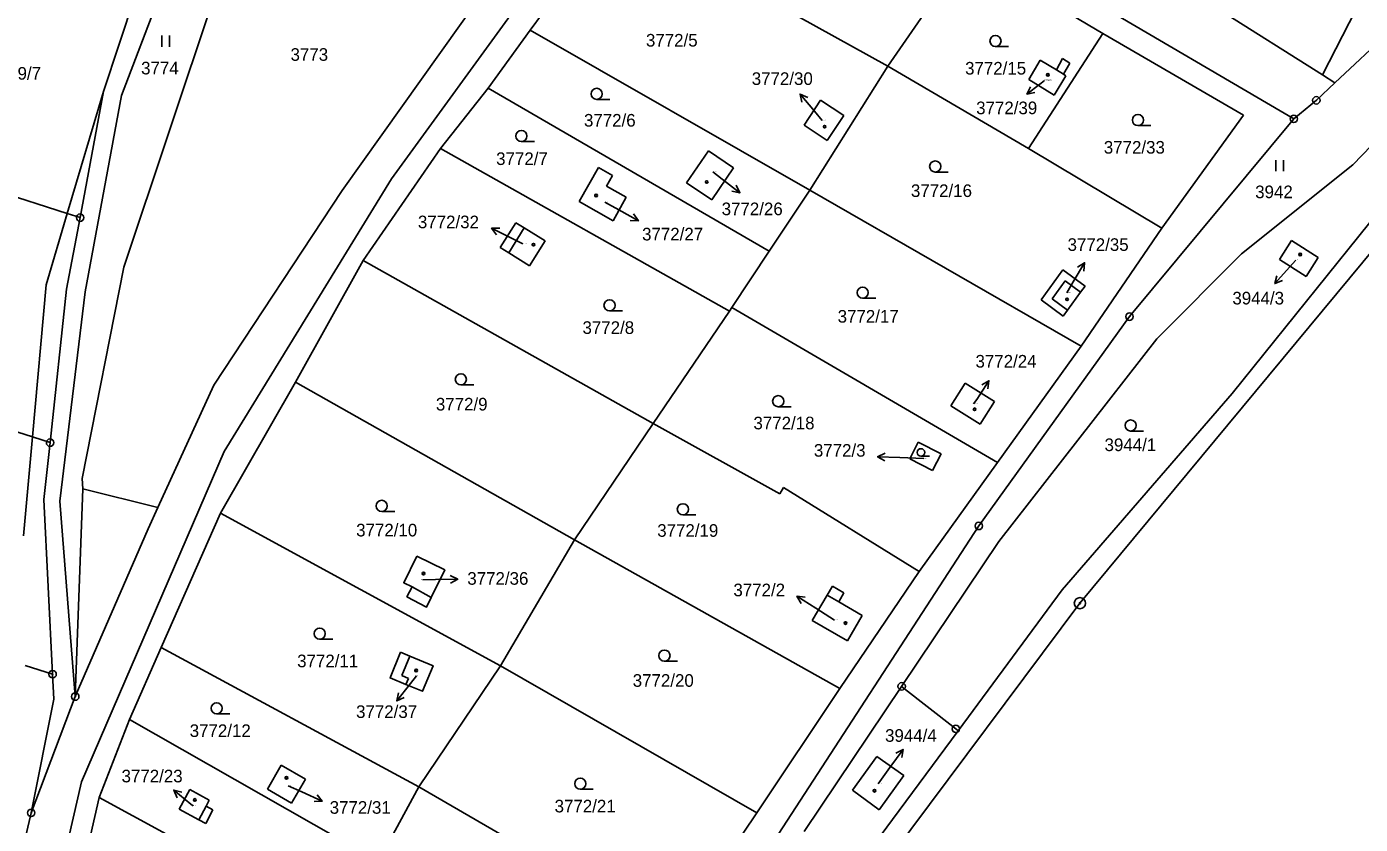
# Model space of a CAD drawing. Extents: x -593183 to -588034, y -1130415 to -1124994.
# Drawn here: x -592165.9 to -591986.4, y -1129394.8 to -1129287.4 of the extents above; entities that cross this region are included whole.
import ezdxf

# ---------------------------------------------------------------- set-up
doc = ezdxf.new("R2010")
doc.units = 0
for name, color, linetype in [('Vrstva 1', 7, 'Continuous'), ('Vrstva 16', 7, 'Continuous'), ('Vrstva 18', 7, 'Continuous'), ('Vrstva 19', 7, 'Continuous'), ('Vrstva 24', 7, 'Continuous'), ('Vrstva 25', 7, 'Continuous'), ('Vrstva 4', 7, 'Continuous')]:
    doc.layers.add(name, color=color, linetype=linetype)

msp = doc.modelspace()

# ---------------------------------------------------------------- linework, layer by layer
at = {"layer": 'Vrstva 1'}
for p, q in [((-591991.53, -1129293.86), (-591952.91, -1129218.61)), ((-592116.8, -1129307.85), (-592076.4, -1129252.25)), ((-592145, -1129264.2), (-592155.57, -1129296.12)), ((-592044.4, -1129271.02), (-591995.38, -1129299.79)), ((-592098.13, -1129287.85), (-592086.76, -1129272.18)), ((-592086.76, -1129272.18), (-592050.02, -1129292.7)), ((-592145.24, -1129275.92), (-592153.15, -1129296.63)), ((-592039.44, -1129277.39), (-592050.02, -1129292.7)), ((-592021.07, -1129288.3), (-592039.44, -1129277.39)), ((-592123.43, -1129309.45), (-592101.67, -1129278.83)), ((-591989.84, -1129294.93), (-591974.47, -1129280.49)), ((-592139.87, -1129280.88), (-592152.85, -1129319.75)), ((-592005.49, -1129285.08), (-591991.53, -1129293.86)), ((-592103.79, -1129295.64), (-592098.13, -1129287.85)), ((-592098.13, -1129287.85), (-592060.52, -1129309.39)), ((-592031.08, -1129303.8), (-592021.07, -1129288.3)), ((-592021.07, -1129288.3), (-592002.16, -1129299.31)), ((-592050.02, -1129292.7), (-592060.52, -1129309.39)), ((-592050.02, -1129292.7), (-592031.08, -1129303.8)), ((-592029.5, -1129291.89), (-592031.05, -1129294.47)), ((-592029.5, -1129291.89), (-592027.32, -1129293.19)), ((-592026.49, -1129291.68), (-592027.32, -1129293.19)), ((-592026.49, -1129291.68), (-592025.54, -1129292.28)), ((-592025.54, -1129292.28), (-592026.36, -1129293.76)), ((-592031.05, -1129294.47), (-592027.65, -1129296.58)), ((-592026.06, -1129293.98), (-592027.65, -1129296.58)), ((-592026.36, -1129293.76), (-592026.06, -1129293.98)), ((-591989.84, -1129294.93), (-591992.35, -1129297.29)), ((-591991.53, -1129293.86), (-591989.84, -1129294.93)), ((-592158.72, -1129313.09), (-592155.57, -1129296.12)), ((-592153.15, -1129296.63), (-592158.02, -1129323.08)), ((-592110.24, -1129303.79), (-592103.79, -1129295.64)), ((-592103.79, -1129295.64), (-592065.98, -1129317.61)), ((-591987.44, -1129306), (-591977.32, -1129295.39)), ((-592061.29, -1129300.64), (-592059.06, -1129297.27)), ((-592059.06, -1129297.27), (-592055.94, -1129299.33)), ((-591972.2, -1129297.61), (-592003.67, -1129336.79)), ((-591995.38, -1129299.79), (-591992.35, -1129297.29)), ((-592055.94, -1129299.33), (-592058.17, -1129302.7)), ((-592024.17, -1129365.01), (-591969.86, -1129299.49)), ((-592017.49, -1129326.42), (-591995.38, -1129299.79)), ((-592002.16, -1129299.31), (-592013.13, -1129314.49)), ((-592058.17, -1129302.7), (-592061.29, -1129300.64)), ((-592120.64, -1129318.86), (-592110.24, -1129303.79)), ((-592110.24, -1129303.79), (-592071.33, -1129325.67)), ((-592013.13, -1129314.49), (-592031.08, -1129303.8)), ((-592074.17, -1129304.09), (-592077.1, -1129308.39)), ((-592070.78, -1129306.4), (-592074.17, -1129304.09)), ((-592178.65, -1129306.72), (-592160.44, -1129312.54)), ((-592091.57, -1129310.93), (-592088.97, -1129306.32)), ((-592088.97, -1129306.32), (-592087.06, -1129307.4)), ((-592087.06, -1129307.4), (-592087.87, -1129308.83)), ((-592073.71, -1129310.7), (-592070.78, -1129306.4)), ((-592002.44, -1129317.98), (-591987.44, -1129306)), ((-592116.8, -1129307.85), (-592139.33, -1129344.6)), ((-592087.87, -1129308.83), (-592085.21, -1129310.33)), ((-592077.1, -1129308.39), (-592073.71, -1129310.7)), ((-592140.74, -1129335.63), (-592123.43, -1129309.45)), ((-592087, -1129313.51), (-592091.57, -1129310.93)), ((-592085.21, -1129310.33), (-592087, -1129313.51)), ((-592065.98, -1129317.61), (-592060.52, -1129309.39)), ((-592060.52, -1129309.39), (-592024, -1129330.4)), ((-592160.44, -1129312.54), (-592158.72, -1129313.09)), ((-592160.55, -1129322.71), (-592158.72, -1129313.09)), ((-592102.18, -1129317.1), (-592100.08, -1129313.78)), ((-592100.08, -1129313.78), (-592098.96, -1129314.48)), ((-592098.96, -1129314.48), (-592096.15, -1129316.23)), ((-592024, -1129330.4), (-592013.13, -1129314.49)), ((-592096.15, -1129316.23), (-592098.25, -1129319.57)), ((-591997.3, -1129318.74), (-591995.69, -1129316.19)), ((-591995.69, -1129316.19), (-591992.09, -1129318.46)), ((-592101.03, -1129317.82), (-592102.18, -1129317.1)), ((-592098.25, -1129319.57), (-592101.03, -1129317.82)), ((-592071, -1129325.17), (-592065.98, -1129317.61)), ((-592013.81, -1129329.4), (-592002.44, -1129317.98)), ((-592152.85, -1129319.75), (-592158.46, -1129348.2)), ((-592129.75, -1129335.26), (-592120.64, -1129318.86)), ((-592120.64, -1129318.86), (-592081.58, -1129340.81)), ((-591993.7, -1129321.01), (-591997.3, -1129318.74)), ((-591992.09, -1129318.46), (-591993.7, -1129321.01)), ((-592029.4, -1129324.18), (-592026.45, -1129320.14)), ((-592026.45, -1129320.14), (-592023.48, -1129322.34)), ((-592162.76, -1129343.39), (-592160.55, -1129322.71)), ((-592158.02, -1129323.08), (-592161.46, -1129351.27)), ((-592024.07, -1129323.14), (-592025.82, -1129325.56)), ((-592023.48, -1129322.34), (-592024.07, -1129323.14)), ((-592071.33, -1129325.67), (-592071, -1129325.17)), ((-592071, -1129325.17), (-592035.27, -1129346.07)), ((-592026.41, -1129326.36), (-592029.4, -1129324.18)), ((-592081.58, -1129340.81), (-592071.33, -1129325.67)), ((-592037.78, -1129354.61), (-592017.49, -1129326.42)), ((-592025.82, -1129325.56), (-592026.41, -1129326.36)), ((-592024, -1129330.4), (-592035.27, -1129346.07)), ((-592035.06, -1129356.7), (-592013.81, -1129329.4)), ((-592187.54, -1129335.39), (-592165.13, -1129342.62)), ((-592148.26, -1129352.12), (-592140.74, -1129335.63)), ((-592139.83, -1129352.88), (-592129.75, -1129335.26)), ((-592129.75, -1129335.26), (-592092.2, -1129356.47)), ((-592041.53, -1129338.43), (-592039.63, -1129335.38)), ((-592039.63, -1129335.38), (-592035.68, -1129337.85)), ((-592035.68, -1129337.85), (-592037.58, -1129340.9)), ((-592026.55, -1129363.2), (-592003.67, -1129336.79)), ((-592037.58, -1129340.9), (-592041.53, -1129338.43)), ((-592092.2, -1129356.47), (-592081.58, -1129340.81)), ((-592081.58, -1129340.81), (-592064.54, -1129350.3)), ((-592165.13, -1129342.62), (-592162.76, -1129343.39)), ((-592162.76, -1129343.39), (-592163.58, -1129351.05)), ((-592047.07, -1129345.57), (-592045.93, -1129343.34)), ((-592045.93, -1129343.34), (-592042.85, -1129344.91)), ((-592139.33, -1129344.6), (-592158.54, -1129389.06)), ((-592042.85, -1129344.91), (-592043.99, -1129347.14)), ((-592043.99, -1129347.14), (-592047.07, -1129345.57)), ((-592035.27, -1129346.07), (-592045.8, -1129360.73)), ((-592158.46, -1129348.2), (-592158.37, -1129349.6)), ((-592158.37, -1129349.6), (-592148.26, -1129352.12)), ((-592064.54, -1129350.3), (-592064.06, -1129349.42)), ((-592064.06, -1129349.42), (-592045.8, -1129360.73)), ((-592162.42, -1129374.58), (-592163.58, -1129351.05)), ((-592161.46, -1129351.27), (-592159.37, -1129377.59)), ((-592148.26, -1129352.12), (-592149.57, -1129355.01)), ((-592139.83, -1129352.88), (-592147.83, -1129370.97)), ((-592139.83, -1129352.88), (-592102.13, -1129373.47)), ((-592149.57, -1129355.01), (-592159.37, -1129377.59)), ((-592091.02, -1129436.58), (-592037.78, -1129354.61)), ((-592102.13, -1129373.47), (-592092.2, -1129356.47)), ((-592092.2, -1129356.47), (-592056.49, -1129376.51)), ((-592048.16, -1129376.21), (-592035.06, -1129356.7)), ((-592056.49, -1129376.51), (-592045.8, -1129360.73)), ((-592058.17, -1129363.91), (-592060.18, -1129367.34)), ((-592056.63, -1129364.81), (-592058.17, -1129363.91)), ((-592053.46, -1129366.67), (-592056.63, -1129364.81)), ((-592040.55, -1129382.18), (-592026.55, -1129363.2)), ((-592058.5, -1129410.99), (-592024.17, -1129365.01)), ((-592055.46, -1129370.1), (-592053.46, -1129366.67)), ((-592060.18, -1129367.34), (-592055.46, -1129370.1)), ((-592147.83, -1129370.97), (-592152.07, -1129380.69)), ((-592147.83, -1129370.97), (-592113.13, -1129389.75)), ((-592115.62, -1129371.63), (-592114.34, -1129372.16)), ((-592166.13, -1129373.41), (-592162.42, -1129374.58)), ((-592102.13, -1129373.47), (-592113.13, -1129389.75)), ((-592102.13, -1129373.47), (-592067.65, -1129393.26)), ((-592162.25, -1129377.93), (-592162.42, -1129374.58)), ((-592067.65, -1129393.26), (-592056.49, -1129376.51)), ((-592061.28, -1129395.75), (-592048.16, -1129376.21)), ((-592048.16, -1129376.21), (-592040.86, -1129381.94)), ((-592165.3, -1129393.25), (-592159.37, -1129377.59)), ((-592165.3, -1129393.25), (-592162.25, -1129377.93)), ((-592152.07, -1129380.69), (-592156.14, -1129391.16)), ((-592152.07, -1129380.69), (-592118.58, -1129399.74)), ((-592040.55, -1129382.18), (-592052.83, -1129398.83)), ((-592040.86, -1129381.94), (-592040.55, -1129382.18)), ((-592054.76, -1129390.21), (-592051.49, -1129385.64)), ((-592051.49, -1129385.64), (-592047.88, -1129388.22)), ((-592133.51, -1129390.05), (-592131.64, -1129386.84)), ((-592131.64, -1129386.84), (-592128.4, -1129388.73)), ((-592047.88, -1129388.22), (-592051.17, -1129392.84)), ((-592158.54, -1129389.06), (-592164.8, -1129416.49)), ((-592130.27, -1129391.94), (-592133.51, -1129390.05)), ((-592128.4, -1129388.73), (-592130.27, -1129391.94)), ((-592118.58, -1129399.74), (-592113.13, -1129389.75)), ((-592113.13, -1129389.75), (-592092.18, -1129401.88)), ((-592156.14, -1129391.16), (-592159.4, -1129405.48)), ((-592156.14, -1129391.16), (-592123.59, -1129408.91)), ((-592145.39, -1129392.74), (-592143.96, -1129390.11)), ((-592143.96, -1129390.11), (-592141.33, -1129391.54)), ((-592141.33, -1129391.54), (-592141.76, -1129392.33)), ((-592051.17, -1129392.84), (-592054.76, -1129390.21)), ((-592167.9, -1129404.18), (-592165.3, -1129393.25)), ((-592142.76, -1129394.17), (-592145.39, -1129392.74)), ((-592140.84, -1129392.83), (-592141.8, -1129394.69)), ((-592141.76, -1129392.33), (-592140.84, -1129392.83)), ((-592078.73, -1129409.66), (-592067.65, -1129393.26)), ((-592141.8, -1129394.69), (-592142.76, -1129394.17))]:
    msp.add_line(p, q, dxfattribs=at)
for points in [[(-592114.04, -1129362.82), (-592115.16, -1129362.26), (-592113.42, -1129358.67)], [(-592113.42, -1129358.67), (-592109.64, -1129360.53), (-592111.48, -1129364.26)], [(-592111.48, -1129364.26), (-592112.11, -1129365.55), (-592114.73, -1129364.15), (-592114.04, -1129362.82)], [(-592114.87, -1129375.94), (-592117.01, -1129375.08), (-592115.62, -1129371.63)], [(-592114.34, -1129372.16), (-592111.22, -1129373.44), (-592112.63, -1129376.88), (-592114.87, -1129375.94)]]:
    msp.add_lwpolyline(points, dxfattribs=at)
at = {"layer": 'Vrstva 16'}
for p, q in [((-592058.86, -1129299.99), (-592059.9, -1129298.75)), ((-592073.58, -1129306.94), (-592072.31, -1129307.91)), ((-592088.1, -1129311.02), (-592086.22, -1129312.06)), ((-592099.13, -1129316.63), (-592100.66, -1129315.86)), ((-591995.1, -1129318.8), (-591995.95, -1129319.75)), ((-592025.95, -1129323.22), (-592025.07, -1129321.74)), ((-592038.47, -1129338.18), (-592038.06, -1129337.56)), ((-592045.19, -1129345.54), (-592048.4, -1129345.41)), ((-592112.58, -1129361.87), (-592110.89, -1129361.84)), ((-592057.2, -1129367.28), (-592059.72, -1129365.69)), ((-592113.46, -1129374.79), (-592114.26, -1129375.81)), ((-592051.31, -1129389.33), (-592049.73, -1129387.14)), ((-592130.7, -1129389.6), (-592128.86, -1129390.43)), ((-592143.52, -1129392.32), (-592143.8, -1129392.09))]:
    msp.add_line(p, q, dxfattribs=at)
at = {"layer": 'Vrstva 24'}
for centre, radius in [((-591992.35, -1129297.29), 0.5), ((-591992.35, -1129297.29), 0.0327), ((-591995.38, -1129299.79), 0.5), ((-591995.38, -1129299.79), 0.0327), ((-592158.72, -1129313.09), 0.5), ((-592158.72, -1129313.09), 0.0327), ((-592017.49, -1129326.42), 0.5), ((-592017.49, -1129326.42), 0.0327), ((-592162.76, -1129343.39), 0.5), ((-592162.76, -1129343.39), 0.0327), ((-592037.78, -1129354.61), 0.5), ((-592037.78, -1129354.61), 0.0327), ((-592024.17, -1129365.01), 0.75), ((-592024.17, -1129365.01), 0.0903), ((-592162.42, -1129374.58), 0.5), ((-592162.42, -1129374.58), 0.0327), ((-592048.16, -1129376.21), 0.5), ((-592159.37, -1129377.59), 0.5), ((-592048.16, -1129376.21), 0.0327), ((-592159.37, -1129377.59), 0.0327), ((-592040.86, -1129381.94), 0.5), ((-592040.86, -1129381.94), 0.0327), ((-592165.3, -1129393.25), 0.5), ((-592165.3, -1129393.25), 0.0327)]:
    msp.add_circle(centre, radius, dxfattribs=at)
at = {"layer": 'Vrstva 25'}
for p, q in [((-592147.71, -1129288.57), (-592147.71, -1129290.07)), ((-592146.69, -1129290.07), (-592146.69, -1129288.57)), ((-592033.78, -1129290.05), (-592035.53, -1129290.05)), ((-592028.99, -1129294.67), (-592031.3, -1129296.44)), ((-592059.9, -1129298.75), (-592061.82, -1129296.45)), ((-592087.45, -1129297.17), (-592089.2, -1129297.17)), ((-592014.61, -1129300.7), (-592016.36, -1129300.7)), ((-592097.58, -1129302.85), (-592099.33, -1129302.85)), ((-591997.79, -1129305.35), (-591997.79, -1129306.85)), ((-591996.77, -1129306.85), (-591996.77, -1129305.35)), ((-592041.89, -1129306.95), (-592043.64, -1129306.95)), ((-592072.31, -1129307.91), (-592069.93, -1129309.73)), ((-592086.22, -1129312.06), (-592083.59, -1129313.51)), ((-592100.66, -1129315.86), (-592103.34, -1129314.52)), ((-592025.07, -1129321.74), (-592023.53, -1129319.16)), ((-591995.95, -1129319.75), (-591997.95, -1129321.98)), ((-592051.65, -1129323.94), (-592053.4, -1129323.94)), ((-592085.72, -1129325.65), (-592087.47, -1129325.65)), ((-592105.73, -1129335.62), (-592107.48, -1129335.62)), ((-592038.06, -1129337.56), (-592036.41, -1129335.05)), ((-592063.02, -1129338.56), (-592064.77, -1129338.56)), ((-592015.59, -1129341.83), (-592017.34, -1129341.83)), ((-592044.39, -1129345.21), (-592045.56, -1129345.21)), ((-592048.4, -1129345.41), (-592051.4, -1129345.28)), ((-592116.38, -1129352.66), (-592118.13, -1129352.66)), ((-592075.85, -1129353.11), (-592077.6, -1129353.11)), ((-592110.89, -1129361.84), (-592107.89, -1129361.79)), ((-592059.72, -1129365.69), (-592062.25, -1129364.08)), ((-592124.72, -1129369.86), (-592126.47, -1129369.86)), ((-592078.33, -1129372.82), (-592080.08, -1129372.82)), ((-592114.26, -1129375.81), (-592116.1, -1129378.18)), ((-592138.59, -1129379.92), (-592140.34, -1129379.92)), ((-592049.73, -1129387.14), (-592047.97, -1129384.71)), ((-592089.66, -1129390.07), (-592091.41, -1129390.07)), ((-592143.8, -1129392.09), (-592146.12, -1129390.19)), ((-592128.86, -1129390.43), (-592126.13, -1129391.67))]:
    msp.add_line(p, q, dxfattribs=at)
for points in [[(-592061.57, -1129297.54), (-592061.82, -1129296.45), (-592060.8, -1129296.89)], [(-592030.23, -1129296.23), (-592031.3, -1129296.44), (-592030.82, -1129295.47)], [(-592070.42, -1129308.73), (-592069.93, -1129309.73), (-592071.02, -1129309.52)], [(-592084.23, -1129312.59), (-592083.59, -1129313.51), (-592084.71, -1129313.46)], [(-592102.67, -1129315.41), (-592103.34, -1129314.52), (-592102.22, -1129314.52)], [(-592024.48, -1129319.77), (-592023.53, -1129319.16), (-592023.62, -1129320.28)], [(-591996.91, -1129321.57), (-591997.95, -1129321.98), (-591997.66, -1129320.91)], [(-592037.38, -1129335.61), (-592036.41, -1129335.05), (-592036.54, -1129336.16)], [(-592050.42, -1129345.83), (-592051.4, -1129345.28), (-592050.38, -1129344.83)], [(-592108.9, -1129361.3), (-592107.89, -1129361.79), (-592108.88, -1129362.3)], [(-592061.68, -1129365.04), (-592062.25, -1129364.08), (-592061.14, -1129364.2)], [(-592115.09, -1129377.7), (-592116.1, -1129378.18), (-592115.88, -1129377.08)], [(-592048.96, -1129385.23), (-592047.97, -1129384.71), (-592048.15, -1129385.81)], [(-592145.66, -1129391.21), (-592146.12, -1129390.19), (-592145.03, -1129390.44)], [(-592126.83, -1129390.8), (-592126.13, -1129391.67), (-592127.24, -1129391.71)]]:
    msp.add_lwpolyline(points, dxfattribs=at)
for centre, radius in [((-592035.53, -1129289.3), 0.75), ((-592028.48, -1129293.86), 0.175), ((-592028.48, -1129293.86), 0.15), ((-592089.2, -1129296.42), 0.75), ((-592016.36, -1129299.95), 0.75), ((-592099.33, -1129302.1), 0.75), ((-592058.52, -1129300.84), 0.175), ((-592058.52, -1129300.84), 0.15), ((-592043.64, -1129306.2), 0.75), ((-592074.39, -1129308.29), 0.175), ((-592074.39, -1129308.29), 0.15), ((-592089.28, -1129310.11), 0.175), ((-592089.28, -1129310.11), 0.15), ((-592097.71, -1129316.73), 0.175), ((-592097.71, -1129316.73), 0.15), ((-591994.52, -1129318.05), 0.175), ((-591994.52, -1129318.05), 0.15), ((-592053.4, -1129323.19), 0.75), ((-592087.47, -1129324.9), 0.75), ((-592025.9, -1129324.09), 0.175), ((-592025.9, -1129324.09), 0.15), ((-592107.48, -1129334.87), 0.75), ((-592064.77, -1129337.81), 0.75), ((-592038.34, -1129338.9), 0.175), ((-592038.34, -1129338.9), 0.15), ((-592017.34, -1129341.08), 0.75), ((-592045.56, -1129344.71), 0.503), ((-592118.13, -1129351.91), 0.75), ((-592077.6, -1129352.36), 0.75), ((-592112.5, -1129361.02), 0.175), ((-592112.5, -1129361.02), 0.15), ((-592126.47, -1129369.11), 0.75), ((-592055.71, -1129367.69), 0.175), ((-592055.71, -1129367.69), 0.15), ((-592080.08, -1129372.07), 0.75), ((-592113.5, -1129374.07), 0.175), ((-592113.5, -1129374.07), 0.15), ((-592140.34, -1129379.17), 0.75), ((-592130.95, -1129388.53), 0.175), ((-592130.95, -1129388.53), 0.15), ((-592091.41, -1129389.32), 0.75), ((-592051.82, -1129390.27), 0.175), ((-592143.27, -1129391.51), 0.175), ((-592143.27, -1129391.51), 0.15), ((-592051.82, -1129390.27), 0.15)]:
    msp.add_circle(centre, radius, dxfattribs=at)
at = {"layer": 'Vrstva 4'}
for p, q in [((-592027.32, -1129293.19), (-592026.36, -1129293.76)), ((-592160.44, -1129312.54), (-592155.57, -1129296.12)), ((-592163.28, -1129322.14), (-592160.44, -1129312.54)), ((-592101.03, -1129317.82), (-592098.96, -1129314.48)), ((-592027.91, -1129324.03), (-592026.16, -1129321.62)), ((-592026.16, -1129321.62), (-592024.07, -1129323.14)), ((-592163.28, -1129322.14), (-592165.13, -1129342.62)), ((-592025.82, -1129325.56), (-592027.91, -1129324.03)), ((-592165.13, -1129342.62), (-592166.34, -1129355.96)), ((-592158.37, -1129349.6), (-592159.37, -1129377.59)), ((-592114.04, -1129362.82), (-592111.48, -1129364.26)), ((-592058.17, -1129363.91), (-592057.47, -1129362.71)), ((-592057.47, -1129362.71), (-592055.93, -1129363.61)), ((-592055.93, -1129363.61), (-592056.63, -1129364.81)), ((-592115.43, -1129374.77), (-592114.34, -1129372.16)), ((-592114.54, -1129375.14), (-592115.43, -1129374.77)), ((-592114.87, -1129375.94), (-592114.54, -1129375.14)), ((-592142.76, -1129394.17), (-592141.76, -1129392.33))]:
    msp.add_line(p, q, dxfattribs=at)

# ---------------------------------------------------------------- texts
at = {"layer": 'Vrstva 16'}
for s, p in [('3769/7', (-592170.93, -1129294.51)), ('3772/30', (-592068.33, -1129295.22)), ('3772/39', (-592038.13, -1129299.16)), ('3772/26', (-592072.38, -1129312.76)), ('3772/32', (-592113.26, -1129314.52)), ('3772/27', (-592083.09, -1129316.16)), ('3772/35', (-592025.83, -1129317.57)), ('3944/3', (-592003.65, -1129324.78)), ('3772/24', (-592038.22, -1129333.28)), ('3772/3', (-592059.97, -1129345.28)), ('3772/36', (-592106.61, -1129362.53)), ('3772/2', (-592070.8, -1129364.08)), ('3772/37', (-592121.58, -1129380.47)), ('3944/4', (-592050.39, -1129383.68)), ('3772/23', (-592153.14, -1129389.14)), ('3772/31', (-592125.13, -1129393.37))]:
    msp.add_text(s, height=1.7, dxfattribs=at).set_placement(p)
at = {"layer": 'Vrstva 18'}
for s, height, p in [('3772/5', 1.7, (-592082.57, -1129290.05)), ('3773', 1.7, (-592130.4, -1129291.97)), ('3774', 1.7, (-592150.51, -1129293.8)), ('3772/15', 1.7, (-592039.62, -1129293.82)), ('3772/6', 1.7, (-592090.91, -1129300.83)), ('3772/33', 1.7, (-592020.95, -1129304.47)), ('3772/7', 1.7, (-592102.73, -1129306)), ('3772/16', 1.7, (-592046.91, -1129310.31)), ('3942', 1.7, (-592000.58, -1129310.47)), ('3772/17', 1.7, (-592056.77, -1129327.23)), ('3772/8', 1.7, (-592091.11, -1129328.75)), ('3772/9', 1.7, (-592110.84, -1129339.06)), ('3772/18', 1.7, (-592068.1, -1129341.6)), ('3944/1', 1.7, (-592020.85, -1129344.53)), ('3772/3', 0.1, (-592045.19, -1129345.54)), ('3772/10', 1.7, (-592121.57, -1129356.02)), ('3772/19', 1.7, (-592081.05, -1129356.07)), ('3772/11', 1.7, (-592129.51, -1129373.64)), ('3772/20', 1.7, (-592084.35, -1129376.27)), ('3772/12', 1.7, (-592143.97, -1129383.03)), ('3772/21', 1.7, (-592094.86, -1129393.19))]:
    msp.add_text(s, height=height, dxfattribs=at).set_placement(p)
at = {"layer": 'Vrstva 19'}
for s, height, p in [('3772/39', 0.2, (-592028.99, -1129294.67)), ('3772/30', 0.1, (-592058.86, -1129299.99)), ('3772/26', 0.1, (-592073.58, -1129306.94)), ('3772/27', 0.1, (-592088.1, -1129311.02)), ('3772/32', 0.1, (-592099.13, -1129316.63)), ('3944/3', 0.1, (-591995.1, -1129318.8)), ('3772/35', 0.1, (-592025.95, -1129323.22)), ('3772/24', 0.1, (-592038.47, -1129338.18)), ('3772/36', 0.1, (-592112.84, -1129361.87)), ('3772/2', 0.1, (-592057.2, -1129367.28)), ('3772/37', 0.1, (-592113.72, -1129374.79)), ('3772/31', 0.1, (-592130.7, -1129389.6)), ('3944/4', 0.1, (-592051.31, -1129389.33)), ('3772/23', 0.1, (-592143.52, -1129392.32))]:
    msp.add_text(s, height=height, dxfattribs=at).set_placement(p)

doc.saveas('drawing.dxf')
